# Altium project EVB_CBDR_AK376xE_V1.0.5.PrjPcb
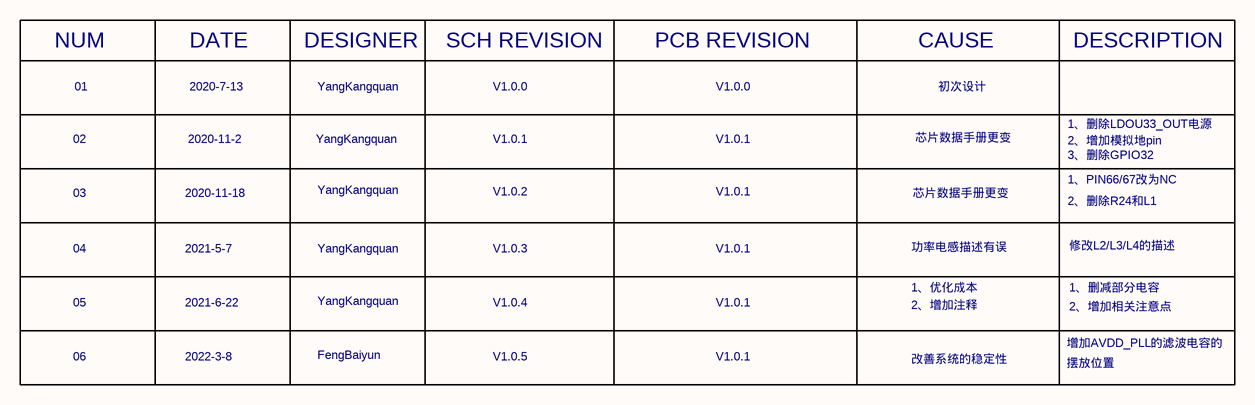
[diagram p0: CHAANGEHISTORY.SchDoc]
7 sheets, 153 parts. Net scope: flat (ports and power ports of the same name join across sheets).
Sheets:
  CHAANGEHISTORY.SchDoc
  BLOCK_DIAGRAM.SchDoc
  INTERFACE_CORE.SchDoc
  AK376xE_POWER.SchDoc
  AK376xE_FLASH.SchDoc
  AK376xE_MIC.SchDoc
  POWER.SchDoc

## Sheet CHAANGEHISTORY.SchDoc: EVB_CBDR_AK376xE_V1.0.5
size A4; Revision: V1.0.5; SheetNumber: 1; SheetTotal: 7

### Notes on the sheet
- NUM
- DATE
- DESIGNER
- SCH REVISION
- PCB REVISION
- CAUSE
- DESCRIPTION
- 01
- 2020-7-13
- YangKangquan
- V1.0.0
- 初次设计
- 02
- 2020-11-2
- V1.0.1
- 芯片数据手册更变
- 1、删除LDOU33_OUT电源
- 2、增加模拟地pin
- 3、删除GPIO32
- 1、PIN66/67改为NC
- 03
- 2020-11-18
- V1.0.2
- 功率电感描述有误
- 2、删除R24和L1
- 修改L2/L3/L4的描述
- 04
- 05
- 2021-5-7
- 2021-6-22
- V1.0.3
- V1.0.4
- 1、优化成本
- 2、增加注释
- 1、删减部分电容
- 2、增加相关注意点
- 06
- 2022-3-8
- FengBaiyun
- V1.0.5
- 改善系统的稳定性
- 增加AVDD_PLL的滤波电容的
- 摆放位置

## Sheet BLOCK_DIAGRAM.SchDoc: EVB_CBDR_AK376xE_V1.0.5
size A4; Revision: V1.0.5; SheetNumber: 2; SheetTotal: 7
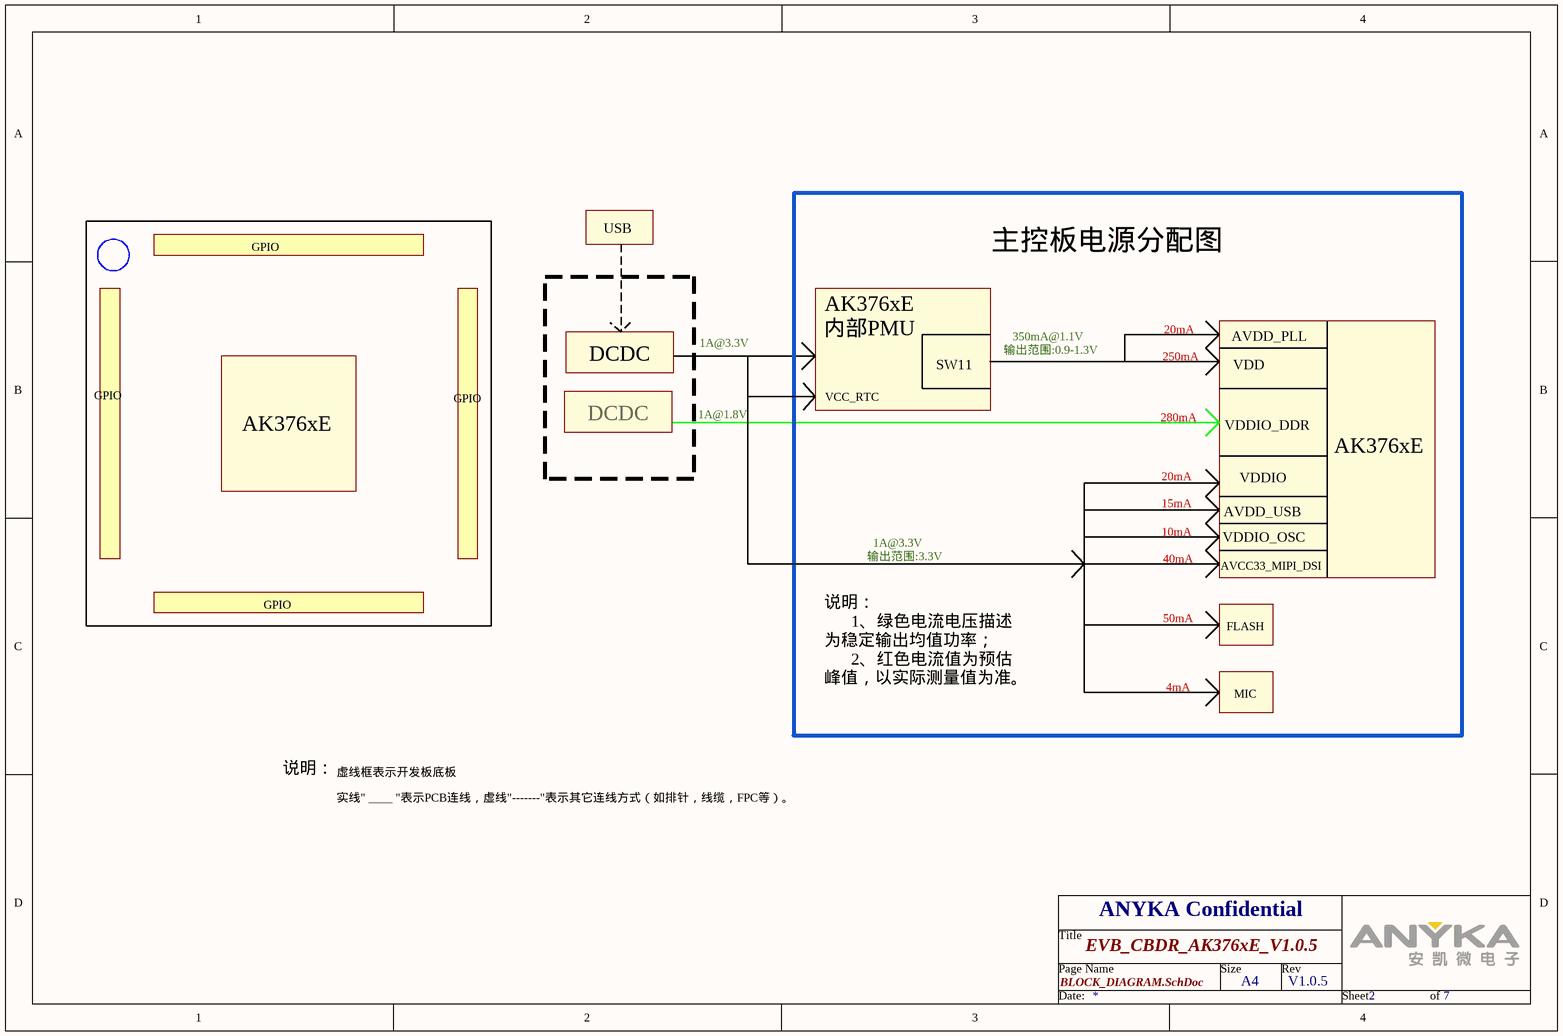
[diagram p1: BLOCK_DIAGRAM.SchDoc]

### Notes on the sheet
- GPIO
- USB
- 主控板电源分配图
- DCDC
- 1A@3.3V
- AK376xE
  内部PMU
- 350mA@1.1V
  输出范围:0.9-1.3V
- 250mA
- 20mA
- AVDD_PLL
- VDD
- AK376xE
- 1A@1.8V
- VCC_RTC
- SW11
- 280mA
- VDDIO_DDR
- 15mA
- AVDD_USB
- VDDIO
- 1A@3.3V
  输出范围:3.3V
- 10mA
- 40mA
- AVCC33_MIPI_DSI
- VDDIO_OSC
- 50mA
- FLASH
- 说明：
  1、绿色电流电压描述为稳定输出均值功率；
  2、红色电流值为预估峰值，以实际测量值为准。
- 4mA
- MIC
- 说明：
- 虚线框表示开发板底板
- 实线" ____ "表示PCB连线，虚线"-------"表示其它连线方式（如排针，线缆，FPC等）。

## Sheet INTERFACE_CORE.SchDoc: EVB_CBDR_AK376xE_V1.0.5
size A4; Revision: V1.0.5; SheetNumber: 3; SheetTotal: 7
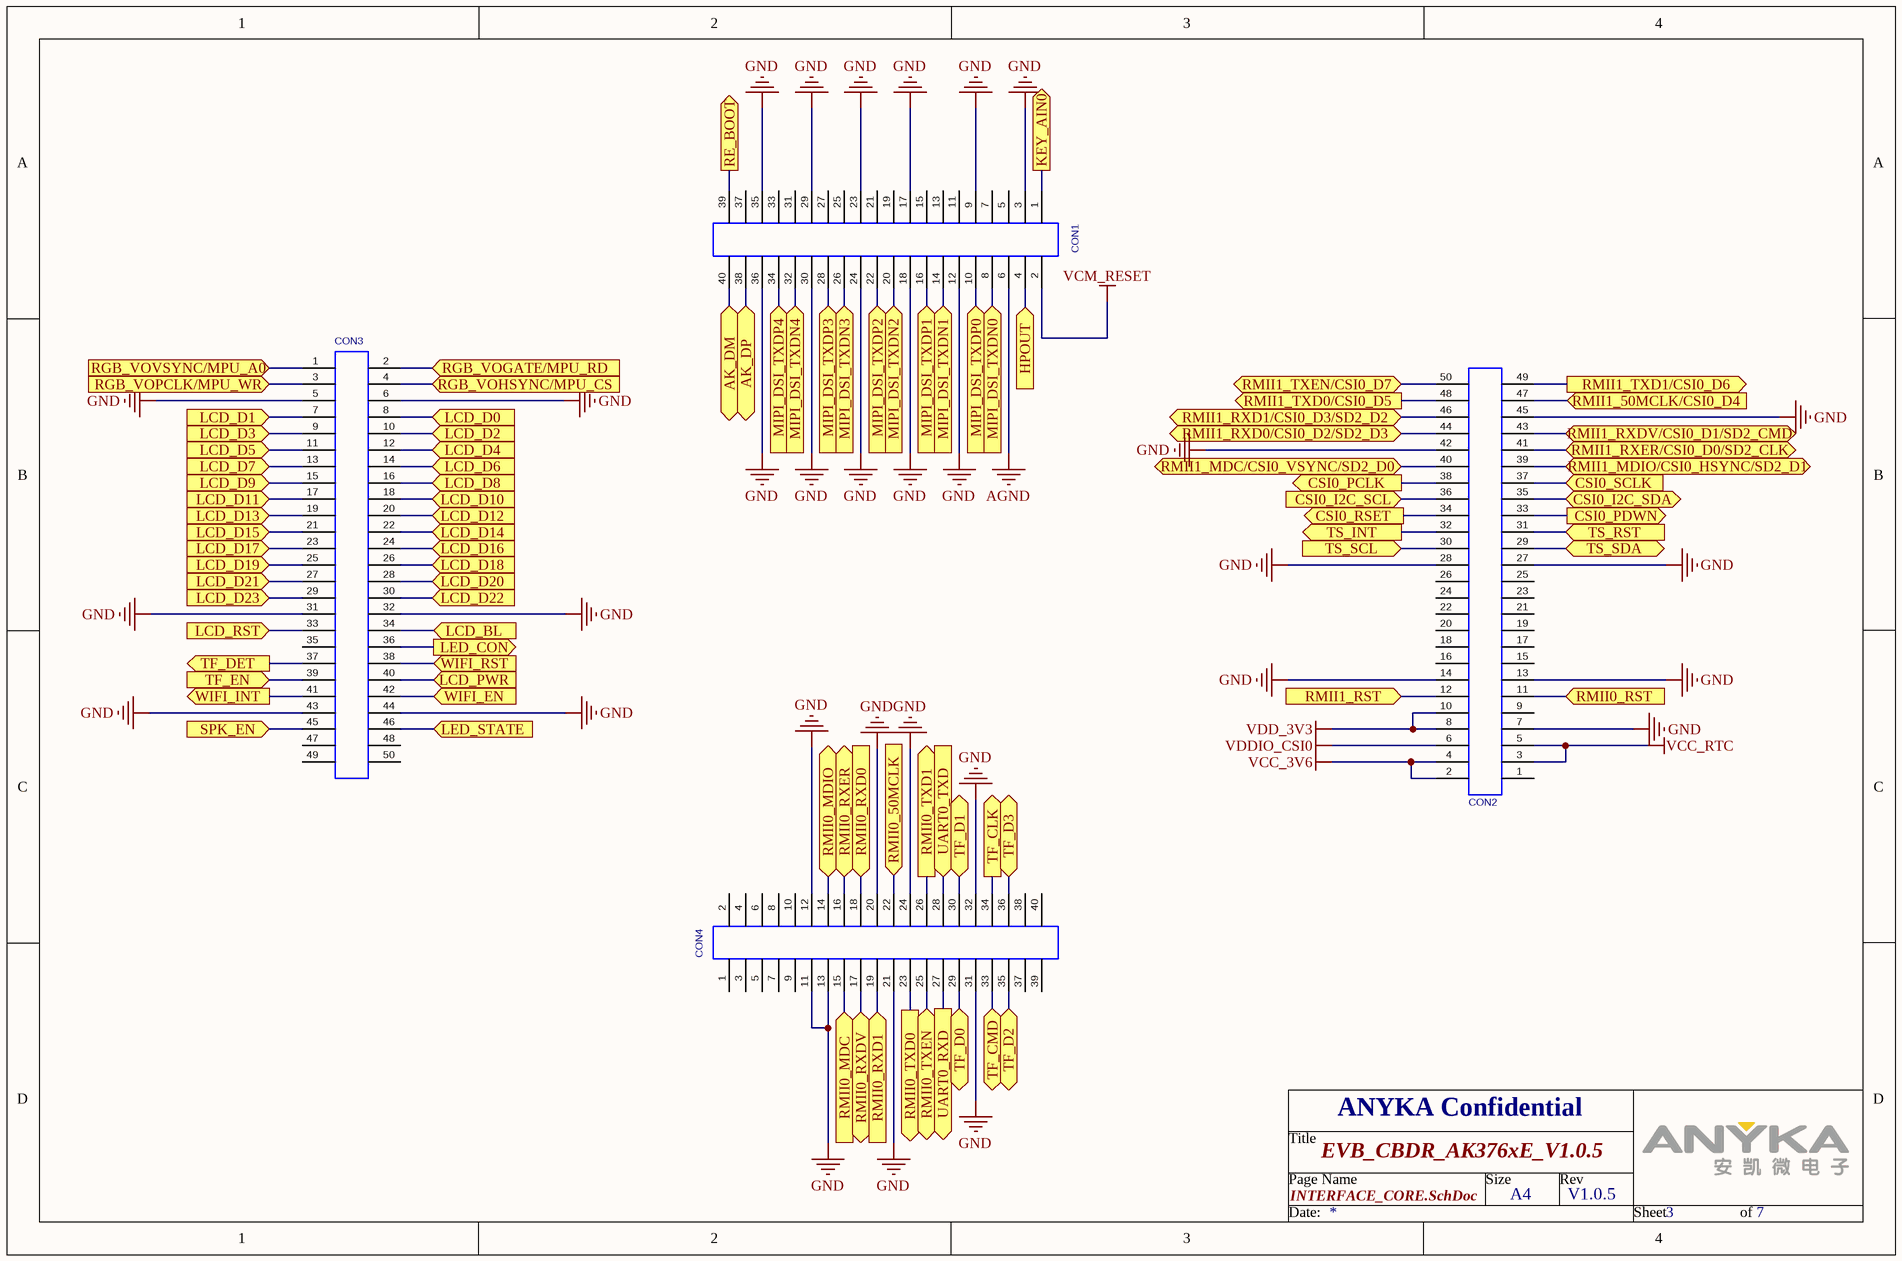
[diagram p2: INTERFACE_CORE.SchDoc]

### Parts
CON1  CON20X2_0MM5_BTB_DF12  [CON20X2_0MM5_BTB_DF12_N]  (value not drawn)
CON2  CON25X2_0MM5_BTB_DF12  [CON25X2_0MM5_BTB_DF12_N]  (value not drawn)
CON3  CON25X2_0MM5_BTB_DF12  [CON25X2_0MM5_BTB_DF12_N]  (value not drawn)
CON4  CON20X2_0MM5_BTB_DF12  [CON20X2_0MM5_BTB_DF12_N]  (value not drawn)

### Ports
AK_DM (bidir), AK_DP (bidir), CSI0_I2C_SCL (in), CSI0_I2C_SDA (bidir), CSI0_PCLK (out), CSI0_PDWN (out), CSI0_RSET (out), CSI0_SCLK (in), HPOUT (in), KEY_AIN0 (out), LCD_BL (in), LCD_D0 (in), LCD_D1 (in), LCD_D2 (in), LCD_D3 (in), LCD_D4 (in), LCD_D5 (in), LCD_D6 (in), LCD_D7 (in), LCD_D8 (in), LCD_D9 (in), LCD_D10 (in), LCD_D11 (in), LCD_D12 (in), LCD_D13 (in), LCD_D14 (in), LCD_D15 (in), LCD_D16 (in), LCD_D17 (in), LCD_D18 (in), LCD_D19 (in), LCD_D20 (in), LCD_D21 (in), LCD_D22 (in), LCD_D23 (in), LCD_PWR (in), LCD_RST (in), LED_CON (out), LED_STATE (in), MIPI_DSI_TXDN0 (in), MIPI_DSI_TXDN1 (in), MIPI_DSI_TXDN2 (in), MIPI_DSI_TXDN3 (in), MIPI_DSI_TXDN4 (in), MIPI_DSI_TXDP0 (in), MIPI_DSI_TXDP1 (in), MIPI_DSI_TXDP2 (in), MIPI_DSI_TXDP3 (in), MIPI_DSI_TXDP4 (in), RE_BOOT (out), RGB_VOGATE/MPU_RD (in), RGB_VOHSYNC/MPU_CS (in), RGB_VOPCLK/MPU_WR (in), RGB_VOVSYNC/MPU_A0 (in), RMII0_50MCLK (in), RMII0_MDC (in), RMII0_MDIO (bidir), RMII0_RST (in), RMII0_RXD0 (in), RMII0_RXD1 (in), RMII0_RXDV (bidir), RMII0_RXER (bidir), RMII0_TXD0 (out), RMII0_TXD1 (out), RMII0_TXEN (bidir), RMII1_50MCLK/CSI0_D4 (in), RMII1_MDC/CSI0_VSYNC/SD2_D0 (bidir), RMII1_MDIO/CSI0_HSYNC/SD2_D1 (bidir), RMII1_RST (in), RMII1_RXD0/CSI0_D2/SD2_D3 (bidir), RMII1_RXD1/CSI0_D3/SD2_D2 (bidir), RMII1_RXDV/CSI0_D1/SD2_CMD (bidir), RMII1_RXER/CSI0_D0/SD2_CLK (bidir), RMII1_TXD0/CSI0_D5 (out), RMII1_TXD1/CSI0_D6 (out), RMII1_TXEN/CSI0_D7 (bidir), SPK_EN (in), TF_CLK (out), TF_CMD (bidir), TF_D0 (bidir), TF_D1 (bidir), TF_D2 (bidir), TF_D3 (bidir), TF_DET (out), TF_EN (in), TS_INT (out), TS_RST (in), TS_SCL (in), TS_SDA (bidir), UART0_RXD (out), UART0_TXD (in), WIFI_EN (in), WIFI_INT (out), WIFI_RST (in)

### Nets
AGND: CON1.6
GND: CON1.3 CON1.9 CON1.12 CON1.17 CON1.18 CON1.23 CON1.24 CON1.29 CON1.30 CON1.35 CON1.36 CON2.7 CON2.13 CON2.14 CON2.27 CON2.28 CON2.42 CON2.45 CON3.5 CON3.6 CON3.31 CON3.32 CON3.43 CON3.44 CON4.11 CON4.12 CON4.13 CON4.20 CON4.21 CON4.24 CON4.31 CON4.32
VCC_3V6: CON2.2 CON2.4
VCC_RTC: CON2.3 CON2.5
VCM_RESET: CON1.2
VDD_3V3: CON2.8 CON2.10
VDDIO_CSI0: CON2.6
AK_DM: CON1.40 ; port AK_DM
AK_DP: CON1.38 ; port AK_DP
CSI0_I2C_SCL: CON2.36 ; port CSI0_I2C_SCL
CSI0_I2C_SDA: CON2.35 ; port CSI0_I2C_SDA
CSI0_PCLK: CON2.38 ; port CSI0_PCLK
CSI0_PDWN: CON2.33 ; port CSI0_PDWN
CSI0_RSET: CON2.34 ; port CSI0_RSET
CSI0_SCLK: CON2.37 ; port CSI0_SCLK
HPOUT: CON1.4 ; port HPOUT
KEY_AIN0: CON1.1 ; port KEY_AIN0
LCD_BL: CON3.34 ; port LCD_BL
LCD_D0: CON3.8 ; port LCD_D0
LCD_D1: CON3.7 ; port LCD_D1
LCD_D2: CON3.10 ; port LCD_D2
LCD_D3: CON3.9 ; port LCD_D3
LCD_D4: CON3.12 ; port LCD_D4
LCD_D5: CON3.11 ; port LCD_D5
LCD_D6: CON3.14 ; port LCD_D6
LCD_D7: CON3.13 ; port LCD_D7
LCD_D8: CON3.16 ; port LCD_D8
LCD_D9: CON3.15 ; port LCD_D9
LCD_D10: CON3.18 ; port LCD_D10
LCD_D11: CON3.17 ; port LCD_D11
LCD_D12: CON3.20 ; port LCD_D12
LCD_D13: CON3.19 ; port LCD_D13
LCD_D14: CON3.22 ; port LCD_D14
LCD_D15: CON3.21 ; port LCD_D15
LCD_D16: CON3.24 ; port LCD_D16
LCD_D17: CON3.23 ; port LCD_D17
LCD_D18: CON3.26 ; port LCD_D18
LCD_D19: CON3.25 ; port LCD_D19
LCD_D20: CON3.28 ; port LCD_D20
LCD_D21: CON3.27 ; port LCD_D21
LCD_D22: CON3.30 ; port LCD_D22
LCD_D23: CON3.29 ; port LCD_D23
LCD_PWR: CON3.40 ; port LCD_PWR
LCD_RST: CON3.33 ; port LCD_RST
LED_CON: CON3.36 ; port LED_CON
LED_STATE: CON3.46 ; port LED_STATE
MIPI_DSI_TXDN0: CON1.8 ; port MIPI_DSI_TXDN0
MIPI_DSI_TXDN1: CON1.14 ; port MIPI_DSI_TXDN1
MIPI_DSI_TXDN2: CON1.20 ; port MIPI_DSI_TXDN2
MIPI_DSI_TXDN3: CON1.26 ; port MIPI_DSI_TXDN3
MIPI_DSI_TXDN4: CON1.32 ; port MIPI_DSI_TXDN4
MIPI_DSI_TXDP0: CON1.10 ; port MIPI_DSI_TXDP0
MIPI_DSI_TXDP1: CON1.16 ; port MIPI_DSI_TXDP1
MIPI_DSI_TXDP2: CON1.22 ; port MIPI_DSI_TXDP2
MIPI_DSI_TXDP3: CON1.28 ; port MIPI_DSI_TXDP3
MIPI_DSI_TXDP4: CON1.34 ; port MIPI_DSI_TXDP4
RGB_VOGATE/MPU_RD: CON3.2 ; port RGB_VOGATE/MPU_RD
RGB_VOHSYNC/MPU_CS: CON3.4 ; port RGB_VOHSYNC/MPU_CS
RGB_VOPCLK/MPU_WR: CON3.3 ; port RGB_VOPCLK/MPU_WR
RGB_VOVSYNC/MPU_A0: CON3.1 ; port RGB_VOVSYNC/MPU_A0
RMII0_50MCLK: CON4.22 ; port RMII0_50MCLK
RMII0_MDC: CON4.15 ; port RMII0_MDC
RMII0_MDIO: CON4.14 ; port RMII0_MDIO
RMII0_RST: CON2.11 ; port RMII0_RST
RMII0_RXD0: CON4.18 ; port RMII0_RXD0
RMII0_RXD1: CON4.19 ; port RMII0_RXD1
RMII0_RXDV: CON4.17 ; port RMII0_RXDV
RMII0_RXER: CON4.16 ; port RMII0_RXER
RMII0_TXD0: CON4.23 ; port RMII0_TXD0
RMII0_TXD1: CON4.26 ; port RMII0_TXD1
RMII0_TXEN: CON4.25 ; port RMII0_TXEN
RMII1_50MCLK/CSI0_D4: CON2.47 ; port RMII1_50MCLK/CSI0_D4
RMII1_MDC/CSI0_VSYNC/SD2_D0: CON2.40 ; port RMII1_MDC/CSI0_VSYNC/SD2_D0
RMII1_MDIO/CSI0_HSYNC/SD2_D1: CON2.39 ; port RMII1_MDIO/CSI0_HSYNC/SD2_D1
RMII1_RST: CON2.12 ; port RMII1_RST
RMII1_RXD0/CSI0_D2/SD2_D3: CON2.44 ; port RMII1_RXD0/CSI0_D2/SD2_D3
RMII1_RXD1/CSI0_D3/SD2_D2: CON2.46 ; port RMII1_RXD1/CSI0_D3/SD2_D2
RMII1_RXDV/CSI0_D1/SD2_CMD: CON2.43 ; port RMII1_RXDV/CSI0_D1/SD2_CMD
RMII1_RXER/CSI0_D0/SD2_CLK: CON2.41 ; port RMII1_RXER/CSI0_D0/SD2_CLK
RMII1_TXD0/CSI0_D5: CON2.48 ; port RMII1_TXD0/CSI0_D5
RMII1_TXD1/CSI0_D6: CON2.49 ; port RMII1_TXD1/CSI0_D6
RMII1_TXEN/CSI0_D7: CON2.50 ; port RMII1_TXEN/CSI0_D7
SPK_EN: CON3.45 ; port SPK_EN
TF_CLK: CON4.34 ; port TF_CLK
TF_CMD: CON4.33 ; port TF_CMD
TF_D0: CON4.29 ; port TF_D0
TF_D1: CON4.30 ; port TF_D1
TF_D2: CON4.35 ; port TF_D2
TF_D3: CON4.36 ; port TF_D3
TF_DET: CON3.37 ; port TF_DET
TF_EN: CON3.39 ; port TF_EN
TS_INT: CON2.32 ; port TS_INT
TS_RST: CON2.31 ; port TS_RST
TS_SCL: CON2.30 ; port TS_SCL
TS_SDA: CON2.29 ; port TS_SDA
UART0_RXD: CON4.27 ; port UART0_RXD
UART0_TXD: CON4.28 ; port UART0_TXD
WIFI_EN: CON3.42 ; port WIFI_EN
WIFI_INT: CON3.41 ; port WIFI_INT
WIFI_RST: CON3.38 ; port WIFI_RST
NetCON1_39: CON1.39 ; port RE_BOOT

Not connected (* = marked no-connect by the designer): CON1 5 7 11 13 15 19 21 25 27 31 33 37; CON2 1 9 15 16 17 18 19 20 21 22 23 24 25 26; CON3 35 47 48 49 50; CON4 1 2 3 4 5 6 7 8 9 10 37 38 39 40

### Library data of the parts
CON1 CON4 = CNBBM4000XX: 0.5mm ，BTB2*20Pin，SMT，公座，H3.0，DF12#(3.0)-40DS-0.5; PCB DECAL: CON20X2_0MM5_BTB_DF12_BOTTOM; Catalog: Connector
CON2 CON3 = CNBBM5000XX: 0.5mm ，BTB2*25Pin，SMT，公座，H3.0，DF12#(3.0)-50DS-0.5; Catalog: Connector

## Sheet AK376xE_POWER.SchDoc: EVB_CBDR_AK376xE_V1.0.5
size A4; Revision: V1.0.5; SheetNumber: 4; SheetTotal: 7
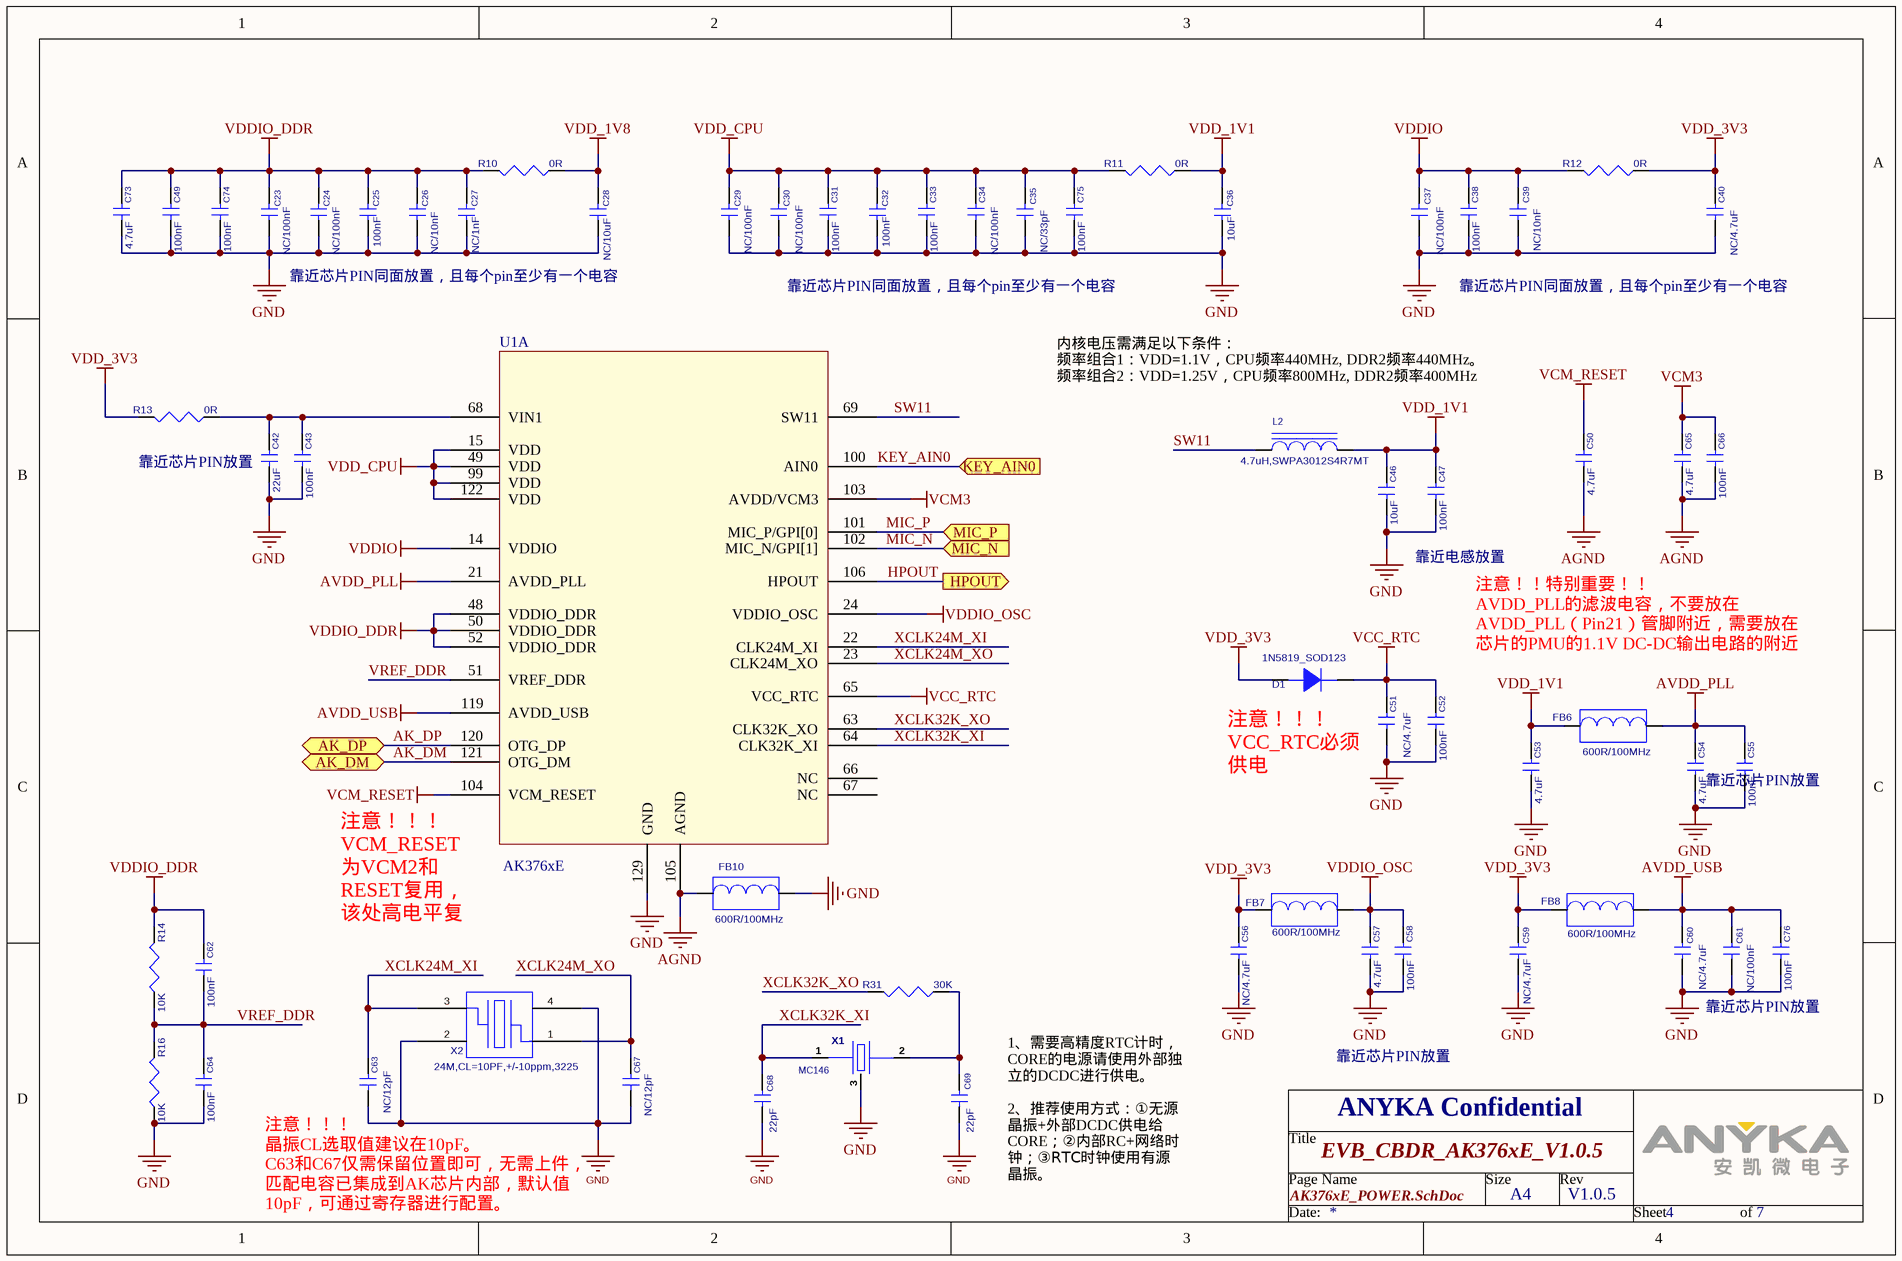
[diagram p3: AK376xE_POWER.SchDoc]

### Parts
C23  NC/100nF  [C0603]
C24  NC/100nF  [C0603]
C25  100nF  [C0603]
C26  NC/10nF  [C0603]
C27  NC/1nF  [C0603]
C28  NC/10uF  [C0603]
C29  NC/100nF  [C0603]
C30  NC/100nF  [C0603]
C31  100nF  [C0402]
C32  100nF  [C0603]
C33  100nF  [C0402]
C34  NC/100nF  [C0402]
C35  NC/33pF  [C0603]
C36  10uF  [C0603]
C37  NC/100nF  [C0603]
C38  100nF  [C0402]
C39  NC/10nF  [C0603]
C40  NC/4.7uF  [C0402]
C42  22uF  [C0805]
C43  100nF  [C0603]
C46  10uF  [C0603]
C47  100nF  [C0603]
C49  100nF  [C0402]
C50  4.7uF  [C0603]
C51  NC/4.7uF  [C0603]
C52  100nF  [C0603]
C53  4.7uF  [C0603]
C54  4.7uF  [C0402]
C55  100nF  [C0402]
C56  NC/4.7uF  [C0603]
C57  4.7uF  [C0402]
C58  100nF  [C0402]
C59  NC/4.7uF  [C0603]
C60  NC/4.7uF  [C0603]
C61  NC/100nF  [C0603]
C62  100nF  [C0603]
C63  NC/12pF  [C0402]
C64  100nF  [C0603]
C65  4.7uF  [C0603]
C66  100nF  [C0603]
C67  NC/12pF  [C0402]
C68  22pF  [C0603]
C69  22pF  [C0603]
C73  4.7uF  [C0402]
C74  100nF  [C0402]
C75  100nF  [C0402]
C76  100nF  [C0402]
D1  1N5819_SOD123  [1N5819_SOD123]  (value not drawn)
FB6  600R/100MHz  [FB0603]
FB7  600R/100MHz  [FB0603]
FB8  600R/100MHz  [FB0603]
FB10  600R/100MHz  [FB0603]
L2  4.7uH,SWPA3012S4R7MT  [L_SWPA3012_3X3MM]
R10  0R  [R0805]
R11  0R  [R0805]
R12  0R  [R0805]
R13  0R  [R0805]
R14  10K  [R0603]
R16  10K  [R0603]
R31  30K  [R0603]
U1  AK376xE  [LQFP128_0MM4_16X16MM]  (part A of 3)
X1  32.768K  [MC146]  (value not drawn)
X2  24M,CL=10PF,+/-10ppm,3225  [3225]

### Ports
AK_DM (bidir), AK_DP (bidir), HPOUT (out), KEY_AIN0 (in), MIC_N (in), MIC_P (in)

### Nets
AGND: C50.2 C65.2 C66.2 FB10.1 U1.105(AGND)
AVDD_PLL: C54.1 C55.1 FB6.2 U1.21(AVDD_PLL)
AVDD_USB: C60.1 C61.1 C76.1 FB8.2 U1.119(AVDD_USB)
GND: C23.1 C24.1 C25.1 C26.1 C27.1 C28.1 C29.1 C30.1 C31.2 C32.1 C33.2 C34.2 C35.1 C36.1 C37.1 C38.2 C39.1 C40.2 C42.2 C43.2 C46.2 C47.2 C49.2 C51.2 C52.2 C53.2 C54.2 C55.2 C56.2 C57.2 C58.2 C59.2 C60.2 C61.2 C63.2 C64.2 C67.2 C68.2 C69.2 C73.2 C74.2 C75.2 C76.2 FB10.2 R16.1 U1.129(GND) X1.3(GND) X2.2 X2.4
VCC_RTC: C51.1 C52.1 D1.K U1.65(VCC_RTC)
VCM3: C65.1 C66.1 U1.103(AVDD/VCM3)
VCM_RESET: C50.1 U1.104(VCM_RESET)
VDD_1V1: C36.2 C46.1 C47.1 C53.1 FB6.1 L2.2 R11.1
VDD_1V8: C28.2 R10.1
VDD_3V3: C40.1 C56.1 C59.1 D1.A FB7.1 FB8.1 R12.1 R13.2
VDD_CPU: C29.2 C30.2 C31.1 C32.2 C33.1 C34.1 C35.2 C75.1 R11.2 U1.15(VDD) U1.49(VDD) U1.99(VDD) U1.122(VDD)
VDDIO: C37.2 C38.1 C39.2 R12.2 U1.14(VDDIO)
VDDIO_DDR: C23.2 C24.2 C25.2 C26.2 C27.2 C49.1 C62.1 C73.1 C74.1 R10.2 R14.2 U1.48(VDDIO_DDR) U1.50(VDDIO_DDR) U1.52(VDDIO_DDR)
VDDIO_OSC: C57.1 C58.1 FB7.2 U1.24(VDDIO_OSC)
AK_DM: U1.121(OTG_DM) ; port AK_DM
AK_DP: U1.120(OTG_DP) ; port AK_DP
HPOUT: U1.106(HPOUT) ; port HPOUT
KEY_AIN0: U1.100(AIN0) ; port KEY_AIN0
MIC_N: U1.102(MIC_N/GPI[1]) ; port MIC_N
MIC_P: U1.101(MIC_P/GPI[0]) ; port MIC_P
SW11: L2.1 U1.69(SW11)
VREF_DDR: C62.2 C64.1 R14.1 R16.2 U1.51(VREF_DDR)
XCLK24M_XI: C63.1 U1.22(CLK24M_XI) X2.3
XCLK24M_XO: C67.1 U1.23(CLK24M_XO) X2.1
XCLK32K_XI: C68.1 U1.64(CLK32K_XI) X1.1
XCLK32K_XO: R31.2 U1.63(CLK32K_XO)
NetC42_1: C42.1 C43.1 R13.1 U1.68(VIN1)
NetC69_1: C69.1 R31.1 X1.2(GND1)

Not connected (* = marked no-connect by the designer): U1 66(NC) 67(_NC)

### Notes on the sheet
- 靠近芯片PIN同面放置，且每个pin至少有一个电容
- (near R13) 靠近芯片PIN放置
- 内核电压需满足以下条件：
  频率组合1：VDD=1.1V，CPU频率440MHz, DDR2频率440MHz。
  频率组合2：VDD=1.25V，CPU频率800MHz, DDR2频率400MHz。
- 靠近电感放置
- 注意！！特别重要！！
  AVDD_PLL的滤波电容，不要放在AVDD_PLL（Pin21）管脚附近，需要放在芯片的PMU的1.1V DC-DC输出电路的附近
- (near C55) 靠近芯片PIN放置
- 注意！！！
  VCC_RTC必须供电
- (near U1) 注意！！！
  VCM_RESET为VCM2和RESET复用，该处高电平复位
- 靠近芯片PIN放置
- (near C69) 1、需要高精度RTC计时，CORE的电源请使用外部独立的DCDC进行供电。
  2、推荐使用方式：①无源晶振+外部DCDC供电给CORE；②内部RC+网络时钟；③RTC时钟使用有源晶振。
- (near C63) 注意！！！
  晶振CL选取值建议在10pF。
  C63和C67仅需保留位置即可，无需上件，匹配电容已集成到AK芯片内部，默认值10pF，可通过寄存器进行配置。

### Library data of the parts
C23 C24 C29 C30 C37 C61 = CC0301040XX: C/C,100nF,25V,+/-5%,0603; Remark: NC; Catalog: 陶瓷电容
C25 C32 C43 C47 C52 C62 C64 C66 = CC0301040XX: C/C,100nF,25V,+/-5%,0603; Catalog: 陶瓷电容
C26 C39 = CC0301032XX: C/C,10nF,50V,+/-10%,0603; Remark: NC; Catalog: 陶瓷电容
C27 = CC0301020XX: C/C,1nF,25V,+/-5%,0603; Remark: NC; Catalog: 陶瓷电容
C28 = CC0301061XX: C/C,10uF,25V,+/-20%,0603; Remark: NC; Catalog: 陶瓷电容
C31 C33 C38 C49 C55 C58 C74-C76 = CC0201040XX: C/C,100nF,25V,+/-5%,0402; Catalog: 陶瓷电容
C34 = CC0201040XX: C/C,100nF,25V,+/-5%,0402; Remark: NC; Catalog: 陶瓷电容
C35 = CC0303300XX: C/C,33pF,25V,+/-5%,0603; Remark: NC; Catalog: 陶瓷电容
C36 C46 = CC0301061XX: C/C,10uF,25V,+/-20%,0603; Catalog: 陶瓷电容
C40 = CC0204751XX: C/C,4.7uF,10V,+/-10%,0402; Remark: NC; Catalog: 陶瓷电容
C42 = CC0502260XX: C/C,22uF,10V,+/-20%,0805; Catalog: 陶瓷电容
C50 C53 C65 = CC0304751XX: C/C,4.7uF,16V,+/-10%,0603; Catalog: 陶瓷电容
C51 C56 C59 C60 = CC0304751XX: C/C,4.7uF,16V,+/-10%,0603; Remark: NC; Catalog: 陶瓷电容
C54 C57 C73 = CC0204751XX: C/C,4.7uF,10V,+/-10%,0402; Catalog: 陶瓷电容
C63 C67 = CC02012R0XX: C/C,12pF,25V,+/-5%,0402; Remark: NC; Catalog: 陶瓷电容
C68 C69 = CC0302200XX: C/C,22pF,25V,+/-5%,0603; Catalog: 陶瓷电容
D1 = DD32SCH04XX: 1N5819_SOD123_1MM7X3MM85; Part Number_AK: DD06SCH00XX; Source_Path: E:\PROJECTS\JVS-H201\LIBRARY1.OLB; CODE: 82268; Catalog: 二极管
FB6-FB8 FB10 = BE0306011XX: BLM18BD601SN1, 600R@100MHz; SOURCE_PATH: D:\PROGRAM FILES\ORCAD\ORCAD_10.5\TOOLS\CAPTURE\LIBRARY\DISCRETE.OLB; Catalog: 贴片磁珠
L2 = WL1C04R70XX: Part Number_AK: WL1C02R20XX; SOURCE_PATH: E:\工作目录\ORCAD原理图库\ORCAD元件库\磁珠&电感.OLB; Catalog: 贴片电感
R10-R13 = CR0500000XX: Res,0R,1/8W,+/-5%,0805; Catalog: 贴片电阻
R14 R16 = CR0310020XX: Res,10K,1/10W,+/-1%,0603; Catalog: 贴片电阻
R31 = CR0303030XX: Res,30K,1/10W,+/-5%,0603; Catalog: 贴片电阻
U1 = 11111111110: AK376xE_LQFP128_0MM4_16X16MM; Catalog: AK芯片
X1 = XR32K77S2XX: 32.768K,CL=12.5pF,20ppm,MC146; Catalog: 晶振
X2 = XR24M00S4XX: Catalog: 晶振

## Sheet AK376xE_FLASH.SchDoc: EVB_CBDR_AK376xE_V1.0.5
size A4; Revision: V1.0.5; SheetNumber: 5; SheetTotal: 7
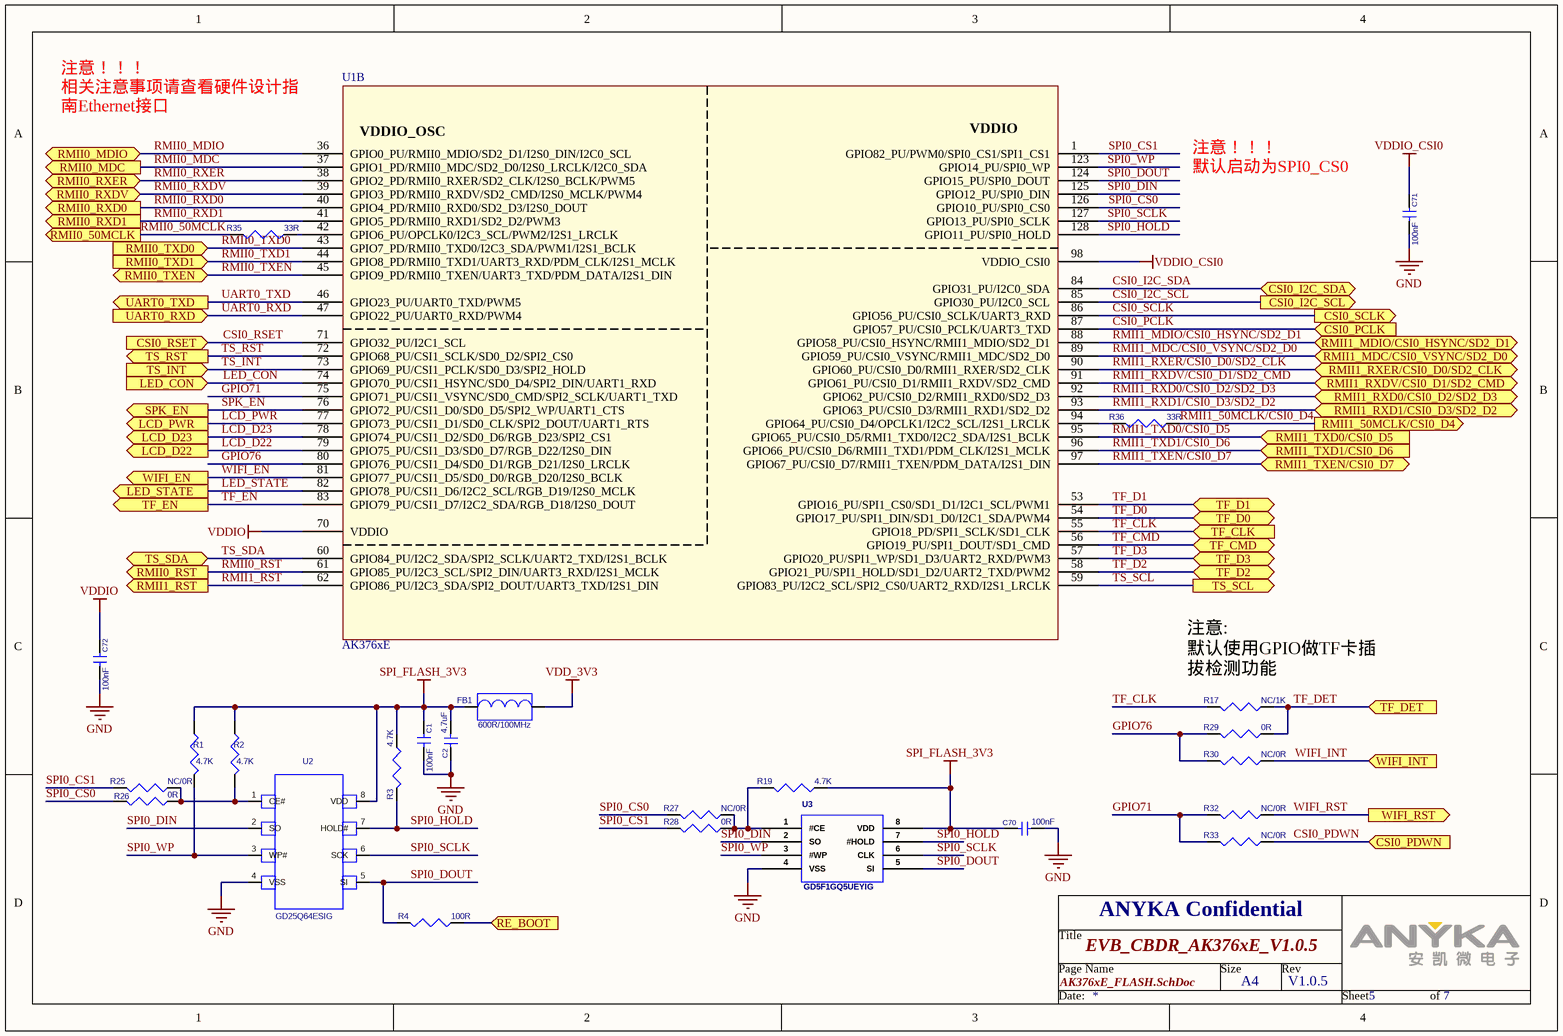
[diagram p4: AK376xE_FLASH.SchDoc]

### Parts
C1  100nF  [C0603]
C2  4.7uF  [C0603]
C70  100nF  [C0603]
C71  100nF  [C0402]
C72  100nF  [C0603]
FB1  600R/100MHz  [FB0603]
R1  4.7K  [R0603]
R2  4.7K  [R0603]
R3  4.7K  [R0603]
R4  100R  [R0603]
R17  NC/1K  [R0603]
R19  4.7K  [R0603]
R25  NC/0R  [R0603]
R26  0R  [R0603]
R27  NC/0R  [R0603]
R28  0R  [R0603]
R29  0R  [R0603]
R30  NC/0R  [R0603]
R32  NC/0R  [R0603]
R33  NC/0R  [R0603]
R35  33R  [R0603]
R36  33R  [R0603]
U1  AK376xE  [LQFP128_0MM4_16X16MM]  (part B of 3)
U2  GD25Q64ESIG  [GD25Q64ESIG_SOP8_1MM27_5X8MM]
U3  GD5F1GQ5UEYIG  [GD5F1GQ5UEYIG_SOP8_1MM27_6X8MM]

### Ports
CSI0_I2C_SCL (out), CSI0_I2C_SDA (bidir), CSI0_PCLK (in), CSI0_PDWN (in), CSI0_RSET (in), CSI0_SCLK (out), LCD_D22 (out), LCD_D23 (out), LCD_PWR (out), LED_CON (in), LED_STATE (out), RE_BOOT (in), RMII0_50MCLK (out), RMII0_MDC (out), RMII0_MDIO (bidir), RMII0_RST (out), RMII0_RXD0 (out), RMII0_RXD1 (out), RMII0_RXDV (bidir), RMII0_RXER (bidir), RMII0_TXD0 (in), RMII0_TXD1 (in), RMII0_TXEN (bidir), RMII1_50MCLK/CSI0_D4 (out), RMII1_MDC/CSI0_VSYNC/SD2_D0 (bidir), RMII1_MDIO/CSI0_HSYNC/SD2_D1 (bidir), RMII1_RST (out), RMII1_RXD0/CSI0_D2/SD2_D3 (bidir), RMII1_RXD1/CSI0_D3/SD2_D2 (bidir), RMII1_RXDV/CSI0_D1/SD2_CMD (bidir), RMII1_RXER/CSI0_D0/SD2_CLK (bidir), RMII1_TXD0/CSI0_D5 (in), RMII1_TXD1/CSI0_D6 (in), RMII1_TXEN/CSI0_D7 (bidir), SPK_EN (out), TF_CLK (in), TF_CMD (bidir), TF_D0 (bidir), TF_D1 (bidir), TF_D2 (bidir), TF_D3 (bidir), TF_DET (in), TF_EN (out), TS_INT (in), TS_RST (out), TS_SCL (out), TS_SDA (bidir), UART0_RXD (in), UART0_TXD (out), WIFI_EN (out), WIFI_INT (in), WIFI_RST (out)

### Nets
GND: C1.2 C2.1 C70.2 C71.2 C72.2 U2.4(VSS) U3.4(VSS)
SPI_FLASH_3V3: C1.1 C2.2 C70.1 FB1.1 R1.1 R2.1 R3.1 R19.1 U2.8(VDD) U3.8(VDD)
VDD_3V3: FB1.2
VDDIO: C72.1 U1.70(VDDIO)
VDDIO_CSI0: C71.1 U1.98(VDDIO_CSI0)
CSI0_I2C_SCL: U1.85(GPIO30_PU/I2C0_SCL) ; port CSI0_I2C_SCL
CSI0_I2C_SDA: U1.84(GPIO31_PU/I2C0_SDA) ; port CSI0_I2C_SDA
CSI0_PCLK: U1.87(GPIO57_PU/CSI0_PCLK/UART3_TXD) ; port CSI0_PCLK
CSI0_PDWN: R33.1 ; port CSI0_PDWN
CSI0_RSET: U1.71(GPIO32_PU/I2C1_SCL) ; port CSI0_RSET
CSI0_SCLK: U1.86(GPIO56_PU/CSI0_SCLK/UART3_RXD) ; port CSI0_SCLK
GPIO71: R32.2 R33.2 U1.75(GPIO71_PU/CSI1_VSYNC/SD0_CMD/SPI2_SCLK/UART1_TXD)
GPIO76: R29.2 R30.2 U1.80(GPIO76_PU/CSI1_D4/SD0_D1/RGB_D21/I2S0_LRCLK)
LCD_D22: U1.79(GPIO75_PU/CSI1_D3/SD0_D7/RGB_D22/I2S0_DIN) ; port LCD_D22
LCD_D23: U1.78(GPIO74_PU/CSI1_D2/SD0_D6/RGB_D23/SPI2_CS1) ; port LCD_D23
LCD_PWR: U1.77(GPIO73_PU/CSI1_D1/SD0_CLK/SPI2_DOUT/UART1_RTS) ; port LCD_PWR
LED_CON: U1.74(GPIO70_PU/CSI1_HSYNC/SD0_D4/SPI2_DIN/UART1_RXD) ; port LED_CON
LED_STATE: U1.82(GPIO78_PU/CSI1_D6/I2C2_SCL/RGB_D19/I2S0_MCLK) ; port LED_STATE
RMII0_50MCLK: R35.2 ; port RMII0_50MCLK
RMII0_MDC: U1.37(GPIO1_PD/RMII0_MDC/SD2_D0/I2S0_LRCLK/I2C0_SDA) ; port RMII0_MDC
RMII0_MDIO: U1.36(GPIO0_PU/RMII0_MDIO/SD2_D1/I2S0_DIN/I2C0_SCL) ; port RMII0_MDIO
RMII0_RST: U1.61(GPIO85_PU/I2C3_SCL/SPI2_DIN/UART3_RXD/I2S1_MCLK) ; port RMII0_RST
RMII0_RXD0: U1.40(GPIO4_PD/RMII0_RXD0/SD2_D3/I2S0_DOUT) ; port RMII0_RXD0
RMII0_RXD1: U1.41(GPIO5_PD/RMII0_RXD1/SD2_D2/PWM3) ; port RMII0_RXD1
RMII0_RXDV: U1.39(GPIO3_PD/RMII0_RXDV/SD2_CMD/I2S0_MCLK/PWM4) ; port RMII0_RXDV
RMII0_RXER: U1.38(GPIO2_PD/RMII0_RXER/SD2_CLK/I2S0_BCLK/PWM5) ; port RMII0_RXER
RMII0_TXD0: U1.43(GPIO7_PD/RMII0_TXD0/I2C3_SDA/PWM1/I2S1_BCLK) ; port RMII0_TXD0
RMII0_TXD1: U1.44(GPIO8_PD/RMII0_TXD1/UART3_RXD/PDM_CLK/I2S1_MCLK) ; port RMII0_TXD1
RMII0_TXEN: U1.45(GPIO9_PD/RMII0_TXEN/UART3_TXD/PDM_DATA/I2S1_DIN) ; port RMII0_TXEN
RMII1_50MCLK/CSI0_D4: R36.1 ; port RMII1_50MCLK/CSI0_D4
RMII1_MDC/CSI0_VSYNC/SD2_D0: U1.89(GPIO59_PU/CSI0_VSYNC/RMII1_MDC/SD2_D0) ; port RMII1_MDC/CSI0_VSYNC/SD2_D0
RMII1_MDIO/CSI0_HSYNC/SD2_D1: U1.88(GPIO58_PU/CSI0_HSYNC/RMII1_MDIO/SD2_D1) ; port RMII1_MDIO/CSI0_HSYNC/SD2_D1
RMII1_RST: U1.62(GPIO86_PU/I2C3_SDA/SPI2_DOUT/UART3_TXD/I2S1_DIN) ; port RMII1_RST
RMII1_RXD0/CSI0_D2/SD2_D3: U1.92(GPIO62_PU/CSI0_D2/RMII1_RXD0/SD2_D3) ; port RMII1_RXD0/CSI0_D2/SD2_D3
RMII1_RXD1/CSI0_D3/SD2_D2: U1.93(GPIO63_PU/CSI0_D3/RMII1_RXD1/SD2_D2) ; port RMII1_RXD1/CSI0_D3/SD2_D2
RMII1_RXDV/CSI0_D1/SD2_CMD: U1.91(GPIO61_PU/CSI0_D1/RMII1_RXDV/SD2_CMD) ; port RMII1_RXDV/CSI0_D1/SD2_CMD
RMII1_RXER/CSI0_D0/SD2_CLK: U1.90(GPIO60_PU/CSI0_D0/RMII1_RXER/SD2_CLK) ; port RMII1_RXER/CSI0_D0/SD2_CLK
RMII1_TXD0/CSI0_D5: U1.95(GPIO65_PU/CSI0_D5/RMI1_TXD0/I2C2_SDA/I2S1_BCLK) ; port RMII1_TXD0/CSI0_D5
RMII1_TXD1/CSI0_D6: U1.96(GPIO66_PU/CSI0_D6/RMII1_TXD1/PDM_CLK/I2S1_MCLK) ; port RMII1_TXD1/CSI0_D6
RMII1_TXEN/CSI0_D7: U1.97(GPIO67_PU/CSI0_D7/RMII1_TXEN/PDM_DATA/I2S1_DIN) ; port RMII1_TXEN/CSI0_D7
SPI0_CS0: R26.2 R27.2 U1.126(GPIO10_PU/SPI0_CS0)
SPI0_CS1: R25.2 R28.2 U1.1(GPIO82_PU/PWM0/SPI0_CS1/SPI1_CS1)
SPI0_DIN: U1.125(GPIO12_PU/SPI0_DIN) U2.2(SO) U3.2(SO)
SPI0_DOUT: R4.2 U1.124(GPIO15_PU/SPI0_DOUT) U2.5(SI) U3.5(SI)
SPI0_HOLD: R3.2 U1.128(GPIO11_PU/SPI0_HOLD) U2.7(HOLD#) U3.7(#HOLD)
SPI0_SCLK: U1.127(GPIO13_PU/SPI0_SCLK) U2.6(SCK) U3.6(CLK)
SPI0_WP: R1.2 U1.123(GPIO14_PU/SPI0_WP) U2.3(WP#) U3.3(#WP)
SPK_EN: U1.76(GPIO72_PU/CSI1_D0/SD0_D5/SPI2_WP/UART1_CTS) ; port SPK_EN
TF_CLK: R17.2 U1.55(GPIO18_PD/SPI1_SCLK/SD1_CLK) ; port TF_CLK
TF_CMD: U1.56(GPIO19_PU/SPI1_DOUT/SD1_CMD) ; port TF_CMD
TF_D0: U1.54(GPIO17_PU/SPI1_DIN/SD1_D0/I2C1_SDA/PWM4) ; port TF_D0
TF_D1: U1.53(GPIO16_PU/SPI1_CS0/SD1_D1/I2C1_SCL/PWM1) ; port TF_D1
TF_D2: U1.58(GPIO21_PU/SPI1_HOLD/SD1_D2/UART2_TXD/PWM2) ; port TF_D2
TF_D3: U1.57(GPIO20_PU/SPI1_WP/SD1_D3/UART2_RXD/PWM3) ; port TF_D3
TF_DET: R17.1 R29.1 ; port TF_DET
TF_EN: U1.83(GPIO79_PU/CSI1_D7/I2C2_SDA/RGB_D18/I2S0_DOUT) ; port TF_EN
TS_INT: U1.73(GPIO69_PU/CSI1_PCLK/SD0_D3/SPI2_HOLD) ; port TS_INT
TS_RST: U1.72(GPIO68_PU/CSI1_SCLK/SD0_D2/SPI2_CS0) ; port TS_RST
TS_SCL: U1.59(GPIO83_PU/I2C2_SCL/SPI2_CS0/UART2_RXD/I2S1_LRCLK) ; port TS_SCL
TS_SDA: U1.60(GPIO84_PU/I2C2_SDA/SPI2_SCLK/UART2_TXD/I2S1_BCLK) ; port TS_SDA
UART0_RXD: U1.47(GPIO22_PU/UART0_RXD/PWM4) ; port UART0_RXD
UART0_TXD: U1.46(GPIO23_PU/UART0_TXD/PWM5) ; port UART0_TXD
WIFI_EN: U1.81(GPIO77_PU/CSI1_D5/SD0_D0/RGB_D20/I2S0_BCLK) ; port WIFI_EN
WIFI_INT: R30.1 ; port WIFI_INT
WIFI_RST: R32.1 ; port WIFI_RST
NetCON1_39: R4.1 ; port RE_BOOT
NetR2_2: R2.2 R25.1 R26.1 U2.1(CE#)
NetR19_2: R19.2 R27.1 R28.1 U3.1(#CE)
NetR35_1: R35.1 U1.42(GPIO6_PU/OPCLK0/I2C3_SCL/PWM2/I2S1_LRCLK)
NetR36_2: R36.2 U1.94(GPIO64_PU/CSI0_D4/OPCLK1/I2C2_SCL/I2S1_LRCLK)

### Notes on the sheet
- (near U1) 注意！！！
  相关注意事项请查看硬件设计指南Ethernet接口
- (near C71) 注意！！！
  默认启动为SPI0_CS0
- (near R17) 注意:
  默认使用GPIO做TF卡插拔检测功能

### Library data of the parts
C1 C70 C72 = CC0301040XX: C/C,100nF,25V,+/-5%,0603; Catalog: 陶瓷电容
C2 = CC0304751XX: C/C,4.7uF,16V,+/-10%,0603; Catalog: 陶瓷电容
C71 = CC0201040XX: C/C,100nF,25V,+/-5%,0402; Catalog: 陶瓷电容
FB1 = BE0306011XX: as FB6 on sheet AK376xE_POWER
R1-R3 R19 = CR0304720XX: Res,4.7K,1/10W,+/-5%,0603; Catalog: 贴片电阻
R4 = CR0301010XX: Res,100R,1/10W,+/-5%,0603; Catalog: 贴片电阻
R17 = CR0301020XX: Res,1K,1/10W,+/-5%,0603; Remark: NC; Catalog: 贴片电阻
R25 R27 R30 R32 R33 = CR0300000XX: Res,0R,1/10W,+/-5%,0603; Remark: NC; Catalog: 贴片电阻
R26 R28 R29 = CR0300000XX: Res,0R,1/10W,+/-5%,0603; Catalog: 贴片电阻
R35 R36 = CR0333R00XX: Res,33R,1/10W,+/-1%,0603; Catalog: 贴片电阻
U1 = 11111111110: as U1 on sheet AK376xE_POWER
U2 = JCSOPAP03XX: IC：NOR Flash, Glga Device, GD25Q64ESIG, SOP8, 8MB, 3.3V; PCB DECAL: GDQ64BSIG_SOP8_1MM27_5X8MM; Catalog: 集成电路
U3 = JCDFNMC19XX: SPI-NAND FLASH,GigaDevice,GD5F1GQ5UEYIG,1Gbit SLC NAND Flash,2.7~3.6V,WSON8.; Source_Path: H:\SNOWBIRD-S\PLATFORM\SBS_LIB.OLB; PCB DECAL: GD5F1GQ4UAYIG_SOP8_1MM27_6X8MM; Catalog: 集成电路

## Sheet AK376xE_MIC.SchDoc: EVB_CBDR_AK376xE_V1.0.5
size A4; Revision: V1.0.5; SheetNumber: 6; SheetTotal: 7
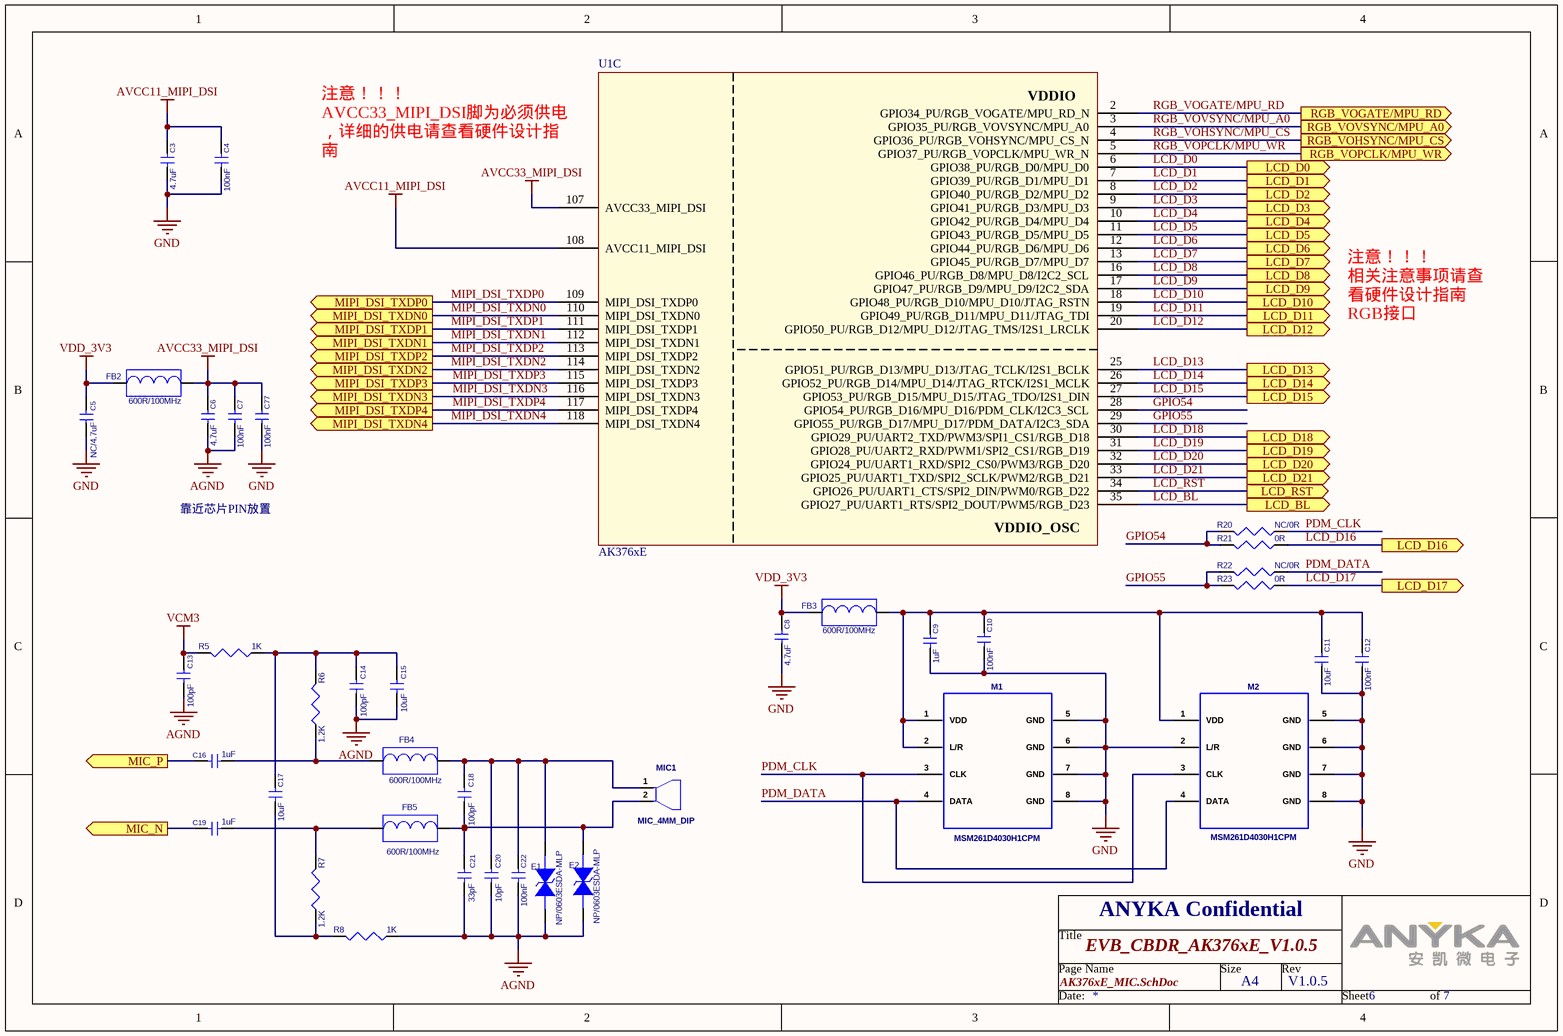
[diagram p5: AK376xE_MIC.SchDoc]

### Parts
C3  4.7uF  [C0402]
C4  100nF  [C0402]
C5  NC/4.7uF  [C0603]
C6  4.7uF  [C0402]
C7  100nF  [C0402]
C8  4.7uF  [C0603]
C9  1uF  [C0603]
C10  100nF  [C0603]
C11  10uF  [C0603]
C12  100nF  [C0603]
C13  100pF  [C0603]
C14  100pF  [C0603]
C15  10uF  [C0603]
C16  1uF  [C0603]
C17  10uF  [C0603]
C18  100pF  [C0603]
C19  1uF  [C0603]
C20  10pF  [C0603]
C21  33pF  [C0603]
C22  100nF  [C0603]
C77  100nF  [C0402]
E1  value NP/0603ESDA-MLP  [ESD0603]  (hidden comment: ESD0603)
E2  value NP/0603ESDA-MLP  [ESD0603]  (hidden comment: ESD0603)
FB2  600R/100MHz  [FB0603]
FB3  600R/100MHz  [FB0603]
FB4  600R/100MHz  [FB0603]
FB5  600R/100MHz  [FB0603]
M1  MSM261D4030H1CPM  [MSM261D4030H1]
M2  MSM261D4030H1CPM  [MSM261D4030H1]
MIC1  MIC_4MM_DIP  [MIC_4MM_DIP]
R5  1K  [R0603]
R6  1.2K  [R0603]
R7  1.2K  [R0603]
R8  1K  [R0603]
R20  NC/0R  [R0603]
R21  0R  [R0603]
R22  NC/0R  [R0603]
R23  0R  [R0603]
U1  AK376xE  [LQFP128_0MM4_16X16MM]  (part C of 3)

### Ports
LCD_BL (out), LCD_D0 (out), LCD_D1 (out), LCD_D2 (out), LCD_D3 (out), LCD_D4 (out), LCD_D5 (out), LCD_D6 (out), LCD_D7 (out), LCD_D8 (out), LCD_D9 (out), LCD_D10 (out), LCD_D11 (out), LCD_D12 (out), LCD_D13 (out), LCD_D14 (out), LCD_D15 (out), LCD_D16 (out), LCD_D17 (out), LCD_D18 (out), LCD_D19 (out), LCD_D20 (out), LCD_D21 (out), LCD_RST (out), MIC_N (out), MIC_P (out), MIPI_DSI_TXDN0 (out), MIPI_DSI_TXDN1 (out), MIPI_DSI_TXDN2 (out), MIPI_DSI_TXDN3 (out), MIPI_DSI_TXDN4 (out), MIPI_DSI_TXDP0 (out), MIPI_DSI_TXDP1 (out), MIPI_DSI_TXDP2 (out), MIPI_DSI_TXDP3 (out), MIPI_DSI_TXDP4 (out), RGB_VOGATE/MPU_RD (out), RGB_VOHSYNC/MPU_CS (out), RGB_VOPCLK/MPU_WR (out), RGB_VOVSYNC/MPU_A0 (out)

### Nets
AGND: C6.2 C7.2 C13.2 C14.2 C15.2 C20.2 C21.2 C22.2 E1.2 E2.2 R8.1
AVCC11_MIPI_DSI: C3.1 C4.1 U1.108(AVCC11_MIPI_DSI)
AVCC33_MIPI_DSI: C6.1 C7.1 C77.1 FB2.2 U1.107(AVCC33_MIPI_DSI)
GND: C3.2 C4.2 C5.1 C8.2 C9.2 C10.2 C11.2 C12.2 C77.2 M1.5(GND) M1.6(GND) M1.7(GND) M1.8(GND) M2.2(L/R) M2.5(GND) M2.6(GND) M2.7(GND) M2.8(GND)
VCM3: C13.1 R5.2
VDD_3V3: C5.2 C8.1 FB2.1 FB3.1
GPIO54: R20.2 R21.2 U1.28(GPIO54_PU/RGB_D16/MPU_D16/PDM_CLK/I2C3_SCL)
GPIO55: R22.2 R23.2 U1.29(GPIO55_PU/RGB_D17/MPU_D17/PDM_DATA/I2C3_SDA)
LCD_BL: U1.35(GPIO27_PU/UART1_RTS/SPI2_DOUT/PWM5/RGB_D23) ; port LCD_BL
LCD_D0: U1.6(GPIO38_PU/RGB_D0/MPU_D0) ; port LCD_D0
LCD_D1: U1.7(GPIO39_PU/RGB_D1/MPU_D1) ; port LCD_D1
LCD_D2: U1.8(GPIO40_PU/RGB_D2/MPU_D2) ; port LCD_D2
LCD_D3: U1.9(GPIO41_PU/RGB_D3/MPU_D3) ; port LCD_D3
LCD_D4: U1.10(GPIO42_PU/RGB_D4/MPU_D4) ; port LCD_D4
LCD_D5: U1.11(GPIO43_PU/RGB_D5/MPU_D5) ; port LCD_D5
LCD_D6: U1.12(GPIO44_PU/RGB_D6/MPU_D6) ; port LCD_D6
LCD_D7: U1.13(GPIO45_PU/RGB_D7/MPU_D7) ; port LCD_D7
LCD_D8: U1.16(GPIO46_PU/RGB_D8/MPU_D8/I2C2_SCL) ; port LCD_D8
LCD_D9: U1.17(GPIO47_PU/RGB_D9/MPU_D9/I2C2_SDA) ; port LCD_D9
LCD_D10: U1.18(GPIO48_PU/RGB_D10/MPU_D10/JTAG_RSTN) ; port LCD_D10
LCD_D11: U1.19(GPIO49_PU/RGB_D11/MPU_D11/JTAG_TDI) ; port LCD_D11
LCD_D12: U1.20(GPIO50_PU/RGB_D12/MPU_D12/JTAG_TMS/I2S1_LRCLK) ; port LCD_D12
LCD_D13: U1.25(GPIO51_PU/RGB_D13/MPU_D13/JTAG_TCLK/I2S1_BCLK) ; port LCD_D13
LCD_D14: U1.26(GPIO52_PU/RGB_D14/MPU_D14/JTAG_RTCK/I2S1_MCLK) ; port LCD_D14
LCD_D15: U1.27(GPIO53_PU/RGB_D15/MPU_D15/JTAG_TDO/I2S1_DIN) ; port LCD_D15
LCD_D16: R21.1 ; port LCD_D16
LCD_D17: R23.1 ; port LCD_D17
LCD_D18: U1.30(GPIO29_PU/UART2_TXD/PWM3/SPI1_CS1/RGB_D18) ; port LCD_D18
LCD_D19: U1.31(GPIO28_PU/UART2_RXD/PWM1/SPI2_CS1/RGB_D19) ; port LCD_D19
LCD_D20: U1.32(GPIO24_PU/UART1_RXD/SPI2_CS0/PWM3/RGB_D20) ; port LCD_D20
LCD_D21: U1.33(GPIO25_PU/UART1_TXD/SPI2_SCLK/PWM2/RGB_D21) ; port LCD_D21
LCD_RST: U1.34(GPIO26_PU/UART1_CTS/SPI2_DIN/PWM0/RGB_D22) ; port LCD_RST
MIC_N: C19.1 ; port MIC_N
MIC_P: C16.1 ; port MIC_P
MIPI_DSI_TXDN0: U1.110(MIPI_DSI_TXDN0) ; port MIPI_DSI_TXDN0
MIPI_DSI_TXDN1: U1.112(MIPI_DSI_TXDN1) ; port MIPI_DSI_TXDN1
MIPI_DSI_TXDN2: U1.114(MIPI_DSI_TXDN2) ; port MIPI_DSI_TXDN2
MIPI_DSI_TXDN3: U1.116(MIPI_DSI_TXDN3) ; port MIPI_DSI_TXDN3
MIPI_DSI_TXDN4: U1.118(MIPI_DSI_TXDN4) ; port MIPI_DSI_TXDN4
MIPI_DSI_TXDP0: U1.109(MIPI_DSI_TXDP0) ; port MIPI_DSI_TXDP0
MIPI_DSI_TXDP1: U1.111(MIPI_DSI_TXDP1) ; port MIPI_DSI_TXDP1
MIPI_DSI_TXDP2: U1.113(MIPI_DSI_TXDP2) ; port MIPI_DSI_TXDP2
MIPI_DSI_TXDP3: U1.115(MIPI_DSI_TXDP3) ; port MIPI_DSI_TXDP3
MIPI_DSI_TXDP4: U1.117(MIPI_DSI_TXDP4) ; port MIPI_DSI_TXDP4
PDM_CLK: M1.3(CLK) M2.3(CLK) R20.1
PDM_DATA: M1.4(DATA) M2.4(DATA) R22.1
RGB_VOGATE/MPU_RD: U1.2(GPIO34_PU/RGB_VOGATE/MPU_RD_N) ; port RGB_VOGATE/MPU_RD
RGB_VOHSYNC/MPU_CS: U1.4(GPIO36_PU/RGB_VOHSYNC/MPU_CS_N) ; port RGB_VOHSYNC/MPU_CS
RGB_VOPCLK/MPU_WR: U1.5(GPIO37_PU/RGB_VOPCLK/MPU_WR_N) ; port RGB_VOPCLK/MPU_WR
RGB_VOVSYNC/MPU_A0: U1.3(GPIO35_PU/RGB_VOVSYNC/MPU_A0) ; port RGB_VOVSYNC/MPU_A0
NetC9_1: C9.1 C10.1 C11.1 C12.1 FB3.2 M1.1(VDD) M1.2(L/R) M2.1(VDD)
NetC14_1: C14.1 C15.1 C17.1 R5.1 R6.2
NetC16_2: C16.2 FB4.1 R6.1
NetC17_2: C17.2 R7.1 R8.2
NetC18_1: C18.1 C20.1 C22.1 E1.1 FB4.2 MIC1.1
NetC18_2: C18.2 C21.1 E2.1 FB5.2 MIC1.2
NetC19_2: C19.2 FB5.1 R7.2

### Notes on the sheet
- (near U1) 注意！！！
  AVCC33_MIPI_DSI脚为必须供电，详细的供电请查看硬件设计指南
- 注意！！！
  相关注意事项请查看硬件设计指南RGB接口
- 靠近芯片PIN放置

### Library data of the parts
C3 C6 = CC0204751XX: C/C,4.7uF,10V,+/-10%,0402; Catalog: 陶瓷电容
C4 C7 C77 = CC0201040XX: C/C,100nF,25V,+/-5%,0402; Catalog: 陶瓷电容
C5 = CC0304751XX: as C51 on sheet AK376xE_POWER
C8 = CC0304751XX: C/C,4.7uF,16V,+/-10%,0603; Catalog: 陶瓷电容
C9 C16 C19 = CC0301055XX: C/C,1uF,16V,+/-10%,0603; Catalog: 陶瓷电容
C10 C12 C22 = CC0301040XX: C/C,100nF,25V,+/-5%,0603; Catalog: 陶瓷电容
C11 C15 C17 = CC0301061XX: C/C,10uF,25V,+/-20%,0603; Catalog: 陶瓷电容
C13 C14 C18 = CC0301010XX: C/C,100pF,25V,+/-5%,0603; Catalog: 陶瓷电容
C20 = CC0301000XX: C/C,10pF,25V,+/-5%,0603; Catalog: 陶瓷电容
C21 = CC0303300XX: C/C,33pF,25V,+/-5%,0603; Catalog: 陶瓷电容
E1 E2 = ED0314000XX: PESD1608H140CR15GPT,0603; ROOM: power; Source_Path: F:\PROJECTFILES\CADENCE\AK9802PLATFORM\AK98XX_MB_V0-0715.DSN; Remark: NC; Catalog: ESD Protectors
FB2-FB5 = BE0306011XX: as FB6 on sheet AK376xE_POWER
M1 M2 = MP4030941XX: MIC, PDM digital output, MSM261D4030H1CPM ,4mm×3mm×1mm; Catalog: Microphone
MIC1 = MIC
R5 R8 = CR0301020XX: Res,1K,1/10W,+/-5%,0603; Catalog: 贴片电阻
R6 R7 = CR0312010XX: Res,1.2K,1/10W,+/-1%,0603; Catalog: 贴片电阻
R20 R22 = CR0300000XX: as R25 on sheet AK376xE_FLASH
R21 R23 = CR0300000XX: Res,0R,1/10W,+/-5%,0603; Catalog: 贴片电阻
U1 = 11111111110: as U1 on sheet AK376xE_POWER

## Sheet POWER.SchDoc: EVB_CBDR_AK376xE_V1.0.5
size A4; Revision: V1.0.5; SheetNumber: 7; SheetTotal: 7
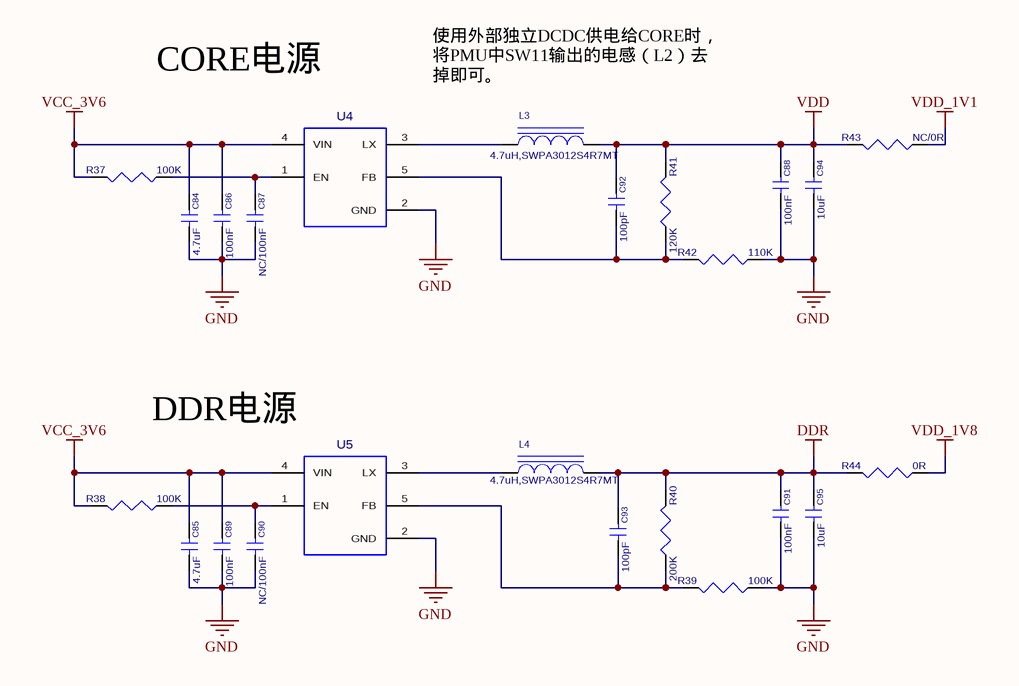
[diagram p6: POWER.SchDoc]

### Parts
C84  4.7uF  [C0402]
C85  4.7uF  [C0402]
C86  100nF  [C0402]
C87  NC/100nF  [C0402]
C88  100nF  [C0402]
C89  100nF  [C0402]
C90  NC/100nF  [C0402]
C91  100nF  [C0402]
C92  100pF  [C0402]
C93  100pF  [C0402]
C94  10uF  [C0603]
C95  10uF  [C0603]
L3  4.7uH,SWPA3012S4R7MT  [L_SWPA3012_3X3MM]
L4  4.7uH,SWPA3012S4R7MT  [L_SWPA3012_3X3MM]
R37  100K  [R0402]
R38  100K  [R0402]
R39  100K  [R0402]
R40  200K  [R0402]
R41  120K  [R0402]
R42  110K  [R0402]
R43  NC/0R  [R0805]
R44  0R  [R0805]
U4  PAM2312_SOT23_5  [PAM2312_SOT23_5]  (value not drawn)
U5  PAM2312_SOT23_5  [PAM2312_SOT23_5]  (value not drawn)

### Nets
DDR: C91.1 C93.1 C95.1 L4.2 R40.2 R44.2
GND: C84.2 C85.2 C86.2 C87.2 C88.2 C89.2 C90.2 C91.2 C94.2 C95.2 R39.1 R42.1 U4.2(GND) U5.2(GND)
VCC_3V6: C84.1 C85.1 C86.1 C89.1 R37.2 R38.2 U4.4(VIN) U5.4(VIN)
VDD: C88.1 C92.1 C94.1 L3.2 R41.2 R43.2
VDD_1V1: R43.1
VDD_1V8: R44.1
NetC87_1: C87.1 R37.1 U4.1(EN)
NetC90_1: C90.1 R38.1 U5.1(EN)
NetC92_2: C92.2 R41.1 R42.2 U4.5(FB)
NetC93_2: C93.2 R39.2 R40.1 U5.5(FB)
NetL3_1: L3.1 U4.3(LX)
NetL4_1: L4.1 U5.3(LX)

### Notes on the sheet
- (near U4) CORE电源
- 使用外部独立DCDC供电给CORE时，将PMU中SW11输出的电感（L2）去掉即可。
- (near U5) DDR电源

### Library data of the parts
C84 C85 = CC0204751XX: C/C,4.7uF,10V,+/-10%,0402; Catalog: 陶瓷电容
C86 C88 C89 C91 = CC0201040XX: C/C,100nF,25V,+/-5%,0402; Catalog: 陶瓷电容
C87 C90 = CC0201040XX: as C34 on sheet AK376xE_POWER
C92 C93 = CC0201010XX: C/C,100pF,25V,+/-5%,0402; Catalog: 陶瓷电容
C94 C95 = CC0301064XX: C/C,10uF,6.3V,+/-20%,0603; Catalog: 陶瓷电容
L3 L4 = WL1C04R70XX: as L2 on sheet AK376xE_POWER
R37-R39 = CR0210030XX: Res,100K,1/16W,+/-1%,0402; Catalog: 贴片电阻
R40 = CR0220030XX: Res,200K,1/16W,+/-1%,0402; Catalog: 贴片电阻
R41 = CR0201240XX: Res,120K,1/16W,+/-1%,0402; Catalog: 贴片电阻
R42 = CR0201140XX: 贴片电阻 通用 res，110k，1/16W,+/-1%,0402；
R43 = CR0500000XX: Res,0R,1/8W,+/-5%,0805; Remark: NC; Catalog: 贴片电阻
R44 = CR0500000XX: Res,0R,1/8W,+/-5%,0805; Catalog: 贴片电阻
U4 U5 = JCSXTPW60XX: PowerIC,PAM,PAM2312AABADJ,SOT23,5pin; Manufacturer #1: XICOR; Sim.Analog.Order: Model$; PCB DECAL: PAM2312_SOT23-5; Catalog: 集成电路

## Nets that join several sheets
AGND: INTERFACE_CORE (CON1.6), AK376xE_POWER (5 pins), AK376xE_MIC (11 pins)
GND: INTERFACE_CORE (32 pins), AK376xE_POWER (49 pins), AK376xE_FLASH (7 pins), AK376xE_MIC (18 pins), POWER (14 pins)
VCC_3V6: INTERFACE_CORE (CON2.2 CON2.4), POWER (8 pins)
VCC_RTC: INTERFACE_CORE (CON2.3 CON2.5), AK376xE_POWER (C51.1 C52.1 D1.K U1.65)
VCM3: AK376xE_POWER (C65.1 C66.1 U1.103), AK376xE_MIC (C13.1 R5.2)
VCM_RESET: INTERFACE_CORE (CON1.2), AK376xE_POWER (C50.1 U1.104)
VDD_1V1: AK376xE_POWER (7 pins), POWER (R43.1)
VDD_1V8: AK376xE_POWER (C28.2 R10.1), POWER (R44.1)
VDD_3V3: INTERFACE_CORE (CON2.8 CON2.10), AK376xE_POWER (8 pins), AK376xE_FLASH (FB1.2), AK376xE_MIC (C5.2 C8.1 FB2.1 FB3.1)
VDDIO: AK376xE_POWER (5 pins), AK376xE_FLASH (C72.1 U1.70)
VDDIO_CSI0: INTERFACE_CORE (CON2.6), AK376xE_FLASH (C71.1 U1.98)
AK_DM: INTERFACE_CORE (CON1.40), AK376xE_POWER (U1.121)
AK_DP: INTERFACE_CORE (CON1.38), AK376xE_POWER (U1.120)
CSI0_I2C_SCL: INTERFACE_CORE (CON2.36), AK376xE_FLASH (U1.85)
CSI0_I2C_SDA: INTERFACE_CORE (CON2.35), AK376xE_FLASH (U1.84)
CSI0_PCLK: INTERFACE_CORE (CON2.38), AK376xE_FLASH (U1.87)
CSI0_PDWN: INTERFACE_CORE (CON2.33), AK376xE_FLASH (R33.1)
CSI0_RSET: INTERFACE_CORE (CON2.34), AK376xE_FLASH (U1.71)
CSI0_SCLK: INTERFACE_CORE (CON2.37), AK376xE_FLASH (U1.86)
HPOUT: INTERFACE_CORE (CON1.4), AK376xE_POWER (U1.106)
KEY_AIN0: INTERFACE_CORE (CON1.1), AK376xE_POWER (U1.100)
LCD_BL: INTERFACE_CORE (CON3.34), AK376xE_MIC (U1.35)
LCD_D0: INTERFACE_CORE (CON3.8), AK376xE_MIC (U1.6)
LCD_D1: INTERFACE_CORE (CON3.7), AK376xE_MIC (U1.7)
LCD_D2: INTERFACE_CORE (CON3.10), AK376xE_MIC (U1.8)
LCD_D3: INTERFACE_CORE (CON3.9), AK376xE_MIC (U1.9)
LCD_D4: INTERFACE_CORE (CON3.12), AK376xE_MIC (U1.10)
LCD_D5: INTERFACE_CORE (CON3.11), AK376xE_MIC (U1.11)
LCD_D6: INTERFACE_CORE (CON3.14), AK376xE_MIC (U1.12)
LCD_D7: INTERFACE_CORE (CON3.13), AK376xE_MIC (U1.13)
LCD_D8: INTERFACE_CORE (CON3.16), AK376xE_MIC (U1.16)
LCD_D9: INTERFACE_CORE (CON3.15), AK376xE_MIC (U1.17)
LCD_D10: INTERFACE_CORE (CON3.18), AK376xE_MIC (U1.18)
LCD_D11: INTERFACE_CORE (CON3.17), AK376xE_MIC (U1.19)
LCD_D12: INTERFACE_CORE (CON3.20), AK376xE_MIC (U1.20)
LCD_D13: INTERFACE_CORE (CON3.19), AK376xE_MIC (U1.25)
LCD_D14: INTERFACE_CORE (CON3.22), AK376xE_MIC (U1.26)
LCD_D15: INTERFACE_CORE (CON3.21), AK376xE_MIC (U1.27)
LCD_D16: INTERFACE_CORE (CON3.24), AK376xE_MIC (R21.1)
LCD_D17: INTERFACE_CORE (CON3.23), AK376xE_MIC (R23.1)
LCD_D18: INTERFACE_CORE (CON3.26), AK376xE_MIC (U1.30)
LCD_D19: INTERFACE_CORE (CON3.25), AK376xE_MIC (U1.31)
LCD_D20: INTERFACE_CORE (CON3.28), AK376xE_MIC (U1.32)
LCD_D21: INTERFACE_CORE (CON3.27), AK376xE_MIC (U1.33)
LCD_D22: INTERFACE_CORE (CON3.30), AK376xE_FLASH (U1.79)
LCD_D23: INTERFACE_CORE (CON3.29), AK376xE_FLASH (U1.78)
LCD_PWR: INTERFACE_CORE (CON3.40), AK376xE_FLASH (U1.77)
LCD_RST: INTERFACE_CORE (CON3.33), AK376xE_MIC (U1.34)
LED_CON: INTERFACE_CORE (CON3.36), AK376xE_FLASH (U1.74)
LED_STATE: INTERFACE_CORE (CON3.46), AK376xE_FLASH (U1.82)
MIC_N: AK376xE_POWER (U1.102), AK376xE_MIC (C19.1)
MIC_P: AK376xE_POWER (U1.101), AK376xE_MIC (C16.1)
MIPI_DSI_TXDN0: INTERFACE_CORE (CON1.8), AK376xE_MIC (U1.110)
MIPI_DSI_TXDN1: INTERFACE_CORE (CON1.14), AK376xE_MIC (U1.112)
MIPI_DSI_TXDN2: INTERFACE_CORE (CON1.20), AK376xE_MIC (U1.114)
MIPI_DSI_TXDN3: INTERFACE_CORE (CON1.26), AK376xE_MIC (U1.116)
MIPI_DSI_TXDN4: INTERFACE_CORE (CON1.32), AK376xE_MIC (U1.118)
MIPI_DSI_TXDP0: INTERFACE_CORE (CON1.10), AK376xE_MIC (U1.109)
MIPI_DSI_TXDP1: INTERFACE_CORE (CON1.16), AK376xE_MIC (U1.111)
MIPI_DSI_TXDP2: INTERFACE_CORE (CON1.22), AK376xE_MIC (U1.113)
MIPI_DSI_TXDP3: INTERFACE_CORE (CON1.28), AK376xE_MIC (U1.115)
MIPI_DSI_TXDP4: INTERFACE_CORE (CON1.34), AK376xE_MIC (U1.117)
NetCON1_39: INTERFACE_CORE (CON1.39), AK376xE_FLASH (R4.1)
RGB_VOGATE/MPU_RD: INTERFACE_CORE (CON3.2), AK376xE_MIC (U1.2)
RGB_VOHSYNC/MPU_CS: INTERFACE_CORE (CON3.4), AK376xE_MIC (U1.4)
RGB_VOPCLK/MPU_WR: INTERFACE_CORE (CON3.3), AK376xE_MIC (U1.5)
RGB_VOVSYNC/MPU_A0: INTERFACE_CORE (CON3.1), AK376xE_MIC (U1.3)
RMII0_50MCLK: INTERFACE_CORE (CON4.22), AK376xE_FLASH (R35.2)
RMII0_MDC: INTERFACE_CORE (CON4.15), AK376xE_FLASH (U1.37)
RMII0_MDIO: INTERFACE_CORE (CON4.14), AK376xE_FLASH (U1.36)
RMII0_RST: INTERFACE_CORE (CON2.11), AK376xE_FLASH (U1.61)
RMII0_RXD0: INTERFACE_CORE (CON4.18), AK376xE_FLASH (U1.40)
RMII0_RXD1: INTERFACE_CORE (CON4.19), AK376xE_FLASH (U1.41)
RMII0_RXDV: INTERFACE_CORE (CON4.17), AK376xE_FLASH (U1.39)
RMII0_RXER: INTERFACE_CORE (CON4.16), AK376xE_FLASH (U1.38)
RMII0_TXD0: INTERFACE_CORE (CON4.23), AK376xE_FLASH (U1.43)
RMII0_TXD1: INTERFACE_CORE (CON4.26), AK376xE_FLASH (U1.44)
RMII0_TXEN: INTERFACE_CORE (CON4.25), AK376xE_FLASH (U1.45)
RMII1_50MCLK/CSI0_D4: INTERFACE_CORE (CON2.47), AK376xE_FLASH (R36.1)
RMII1_MDC/CSI0_VSYNC/SD2_D0: INTERFACE_CORE (CON2.40), AK376xE_FLASH (U1.89)
RMII1_MDIO/CSI0_HSYNC/SD2_D1: INTERFACE_CORE (CON2.39), AK376xE_FLASH (U1.88)
RMII1_RST: INTERFACE_CORE (CON2.12), AK376xE_FLASH (U1.62)
RMII1_RXD0/CSI0_D2/SD2_D3: INTERFACE_CORE (CON2.44), AK376xE_FLASH (U1.92)
RMII1_RXD1/CSI0_D3/SD2_D2: INTERFACE_CORE (CON2.46), AK376xE_FLASH (U1.93)
RMII1_RXDV/CSI0_D1/SD2_CMD: INTERFACE_CORE (CON2.43), AK376xE_FLASH (U1.91)
RMII1_RXER/CSI0_D0/SD2_CLK: INTERFACE_CORE (CON2.41), AK376xE_FLASH (U1.90)
RMII1_TXD0/CSI0_D5: INTERFACE_CORE (CON2.48), AK376xE_FLASH (U1.95)
RMII1_TXD1/CSI0_D6: INTERFACE_CORE (CON2.49), AK376xE_FLASH (U1.96)
RMII1_TXEN/CSI0_D7: INTERFACE_CORE (CON2.50), AK376xE_FLASH (U1.97)
SPK_EN: INTERFACE_CORE (CON3.45), AK376xE_FLASH (U1.76)
TF_CLK: INTERFACE_CORE (CON4.34), AK376xE_FLASH (R17.2 U1.55)
TF_CMD: INTERFACE_CORE (CON4.33), AK376xE_FLASH (U1.56)
TF_D0: INTERFACE_CORE (CON4.29), AK376xE_FLASH (U1.54)
TF_D1: INTERFACE_CORE (CON4.30), AK376xE_FLASH (U1.53)
TF_D2: INTERFACE_CORE (CON4.35), AK376xE_FLASH (U1.58)
TF_D3: INTERFACE_CORE (CON4.36), AK376xE_FLASH (U1.57)
TF_DET: INTERFACE_CORE (CON3.37), AK376xE_FLASH (R17.1 R29.1)
TF_EN: INTERFACE_CORE (CON3.39), AK376xE_FLASH (U1.83)
TS_INT: INTERFACE_CORE (CON2.32), AK376xE_FLASH (U1.73)
TS_RST: INTERFACE_CORE (CON2.31), AK376xE_FLASH (U1.72)
TS_SCL: INTERFACE_CORE (CON2.30), AK376xE_FLASH (U1.59)
TS_SDA: INTERFACE_CORE (CON2.29), AK376xE_FLASH (U1.60)
UART0_RXD: INTERFACE_CORE (CON4.27), AK376xE_FLASH (U1.47)
UART0_TXD: INTERFACE_CORE (CON4.28), AK376xE_FLASH (U1.46)
WIFI_EN: INTERFACE_CORE (CON3.42), AK376xE_FLASH (U1.81)
WIFI_INT: INTERFACE_CORE (CON3.41), AK376xE_FLASH (R30.1)
WIFI_RST: INTERFACE_CORE (CON3.38), AK376xE_FLASH (R32.1)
